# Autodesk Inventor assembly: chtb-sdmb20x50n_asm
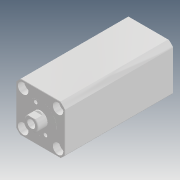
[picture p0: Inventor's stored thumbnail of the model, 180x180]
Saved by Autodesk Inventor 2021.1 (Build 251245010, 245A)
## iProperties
Company: Microsoft
Created: 2018-05
Part Number: chtb-sdmb20x50n_asm
Description: STEP AP214
Document SubType Name: Assembly
Designer: user
Title: chtb-sdmb20x50n_asm.STEP
Author: Windows
Revision Number: ÈÎºÎ
Sending System: SolidWorks 2015
Preprocessor: SwSTEP 2.0
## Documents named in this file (4)
- D:\Vault_2016\Projekty\Clamptek\Hydraulic\CHTB\CHTB-20\Inventor\CHTB-SDMB20x50N\chtb-sdmb20x50n_asm.iam
- D:\Vault_2016\Projekty\Clamptek\Hydraulic\CHTB\CHTB-20\Inventor\CHTB-SDMB20x50N\CHTB-SDMB20X50NBT.ipt
- D:\Vault_2016\Projekty\Clamptek\Hydraulic\CHTB\CHTB-20\Inventor\CHTB-SDMB20x50N\CHTB-SDMB20X50NHSG.ipt
- D:\Vault_2016\Projekty\Clamptek\Hydraulic\CHTB\CHTB-20\Inventor\CHTB-SDMB20x50N\QG_3.ipt
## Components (3 placed, 3 different names)
1. CHTB-SDMB20X50NBT_1
2. CHTB-SDMB20X50NHSG_2
3. QG_3_3
